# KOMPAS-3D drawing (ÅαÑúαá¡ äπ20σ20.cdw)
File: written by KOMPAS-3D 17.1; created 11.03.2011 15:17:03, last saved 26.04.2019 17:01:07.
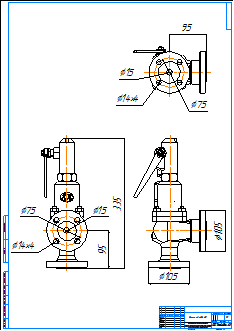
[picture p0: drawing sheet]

Title block, sheet 1: name: Прегран Ду20х20; material: Внимание! Данный продукт является объектом авторского права ООО «Торговый Дом АДЛ». / Запрещается изменение, копирование, распространение / (в том числе путем копирования на другие сайты и ресурсы в Интернете) / или любое иное использование информации и объектов без предварительного / согласия правообладателя (ООО «Торговый Дом АДЛ»).; scale: 1:1; sheets: 1; organisation: ООО "Торговый дом АДЛ"; sheet format: A1; stored path: C:\Users\tra\Desktop\2д чертежи\Предохранительные клапаны ПРЕГРАН\ПРЕГРАН 096\ПРЕГРАН КПП 096-03-40\KOMPAS 2D\Прегран Ду20х20.cdw

Views: Спереди 1, Проекционный вид 2, Проекционный вид 3
Dimensions and other numbers on the sheet: 95; 335; 105; 75; 14; 15; 1:1; 1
